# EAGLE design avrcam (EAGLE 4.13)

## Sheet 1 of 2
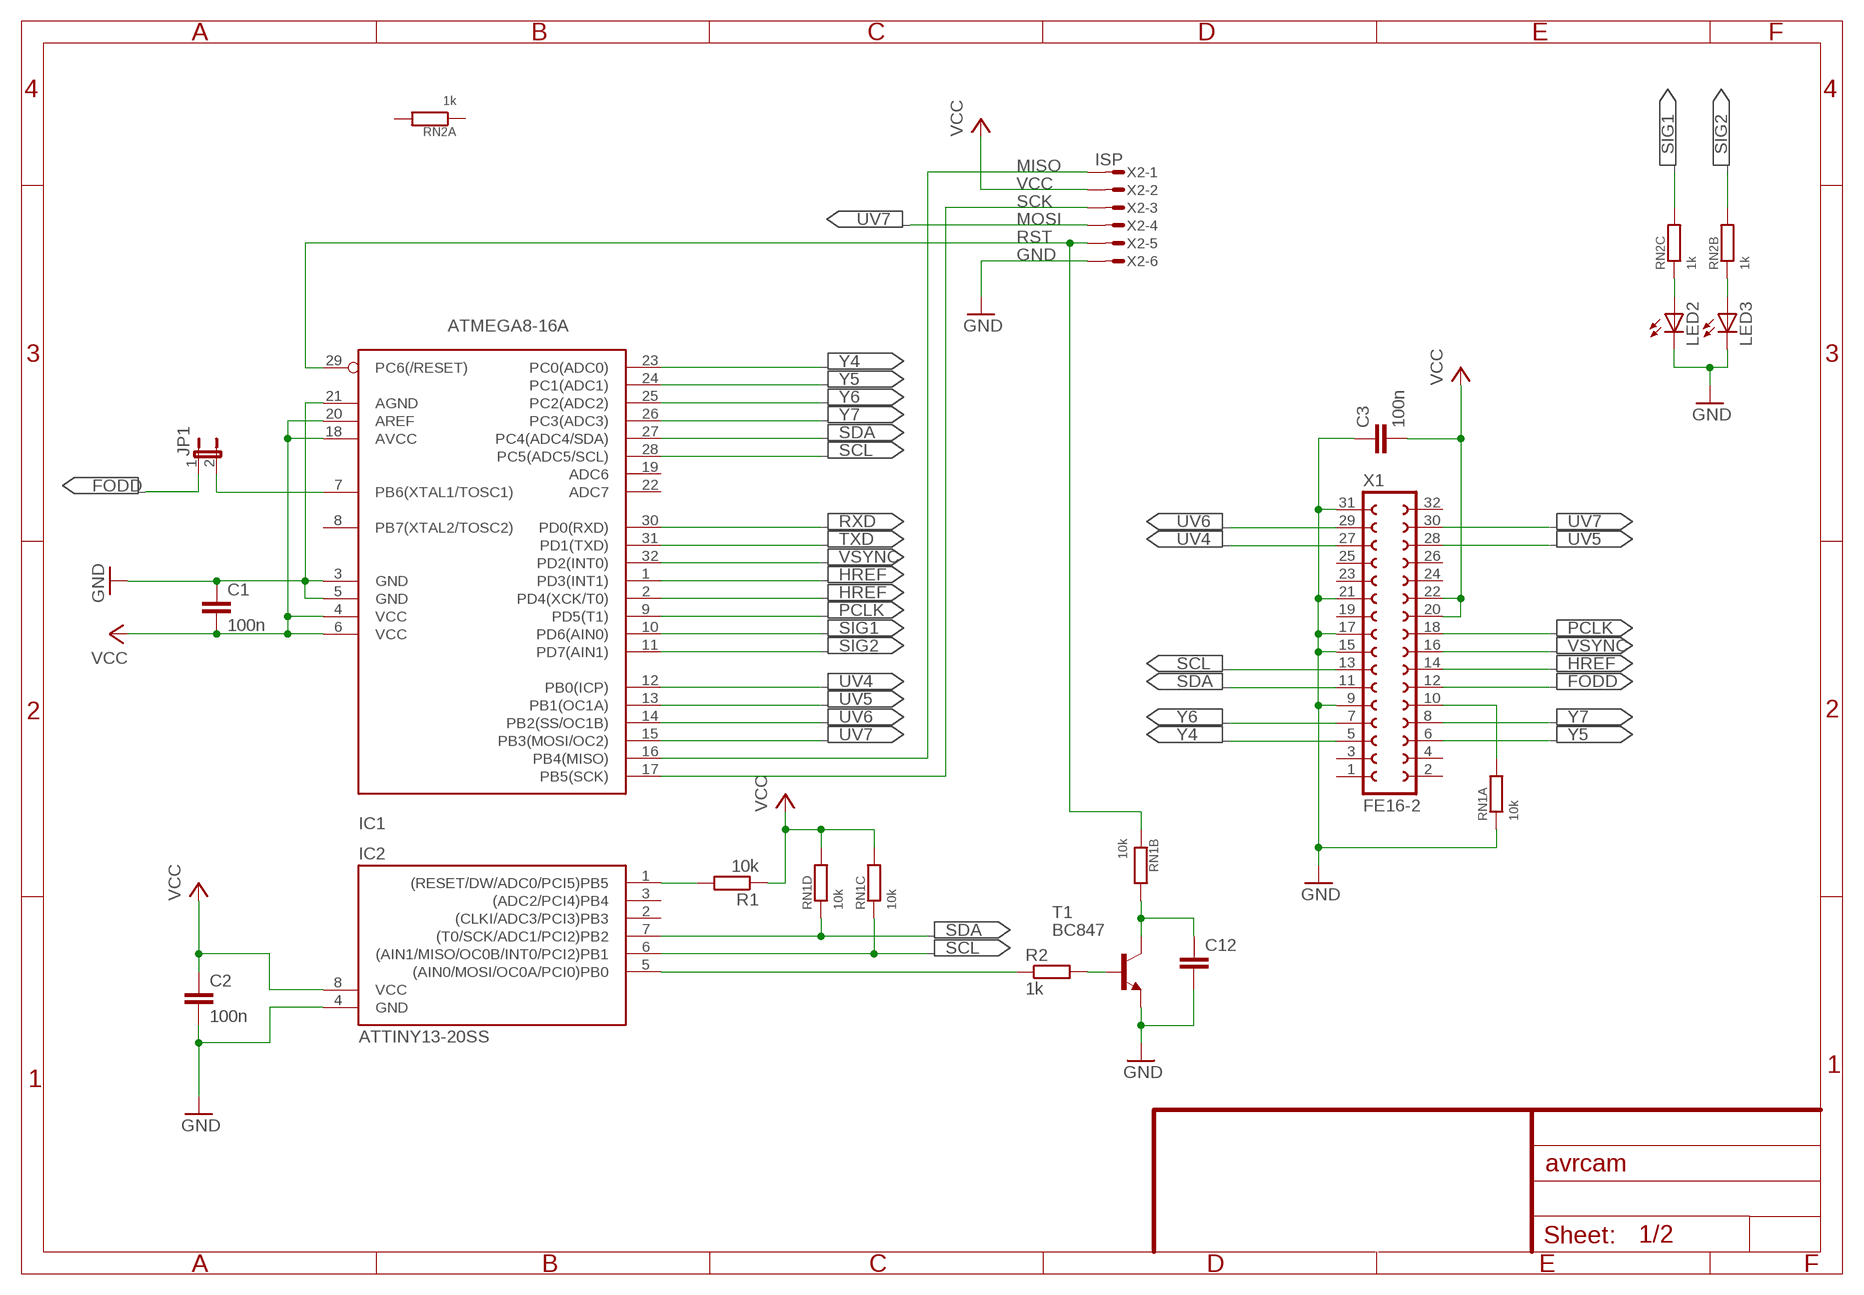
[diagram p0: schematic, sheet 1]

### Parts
C1  100n  C-EUC0603K  [C0603K]
C2  100n  C-EUC0603K  [C0603K]
C3  100n  C-EUC0603K  [C0603K]
C12  C-EUC0603K  [C0603K]
IC1  ATMEGA8-16A  [TQFP32-08]
IC2  ATTINY13-20SS  [SO08]
JP1  JP1E  [JP1]
LED2  LEDCHIPLED_1206  [CHIPLED_1206]
LED3  LEDCHIPLED_1206  [CHIPLED_1206]
R1  10k  R-EU_R0805  [R0805]
R2  1k  R-EU_R0805  [R0805]
RN1  10k  SMDNET4SINGLE  [SMDNET4]
RN2  1k  SMDNET4SINGLE  [SMDNET4]
T1  BC847  [SOT23]
X1  FE16-2  [FE16-2]
X2  ISP  MICROMATCH-6  [MICROMATCH-6]

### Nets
FODD: JP1.1 X1.12
GND: C1.1 C2.2 C3.1 C12.2 IC1.3(GND) IC1.5(GND) IC1.21(AGND) IC2.4(GND) LED2.C LED3.C RN1.1 T1.2(E) X1.9 X1.15 X1.17 X1.21 X1.31 X2.6 ; also sheet 2
HREF: IC1.1(PD3(INT1)) IC1.2(PD4(XCK/T0)) X1.14
MISO: IC1.16(PB4(MISO)) X2.1
N$1: IC2.1((RESET/DW/ADC0/PCI5)PB5) R1.2
N$2: IC1.7(PB6(XTAL1/TOSC1)) JP1.2
N$6: IC2.5((AIN0/MOSI/OC0A/PCI0)PB0) R2.1
N$9: R2.2 T1.1(B)
N$14: C12.1 RN1.7 T1.3(C)
N$15: LED3.A RN2.2
N$16: LED2.A RN2.3
N$18: RN1.8 X1.10
PCLK: IC1.9(PD5(T1)) X1.18
RST: IC1.29(PC6(/RESET)) RN1.2 X2.5
RXD: IC1.30(PD0(RXD)) ; also sheet 2
SCK: IC1.17(PB5(SCK)) X2.3
SCL: IC1.28(PC5(ADC5/SCL)) IC2.6((AIN1/MISO/OC0B/INT0/PCI2)PB1) RN1.3 X1.13
SDA: IC1.27(PC4(ADC4/SDA)) IC2.7((T0/SCK/ADC1/PCI2)PB2) RN1.4 X1.11
SIG1: IC1.10(PD6(AIN0)) RN2.6
SIG2: IC1.11(PD7(AIN1)) RN2.7
TXD: IC1.31(PD1(TXD)) ; also sheet 2
UV4: IC1.12(PB0(ICP)) X1.27
UV5: IC1.13(PB1(OC1A)) X1.28
UV6: IC1.14(PB2(SS/OC1B)) X1.29
UV7: IC1.15(PB3(MOSI/OC2)) X1.30 X2.4
VCC: C1.2 C2.1 C3.2 IC1.4(VCC) IC1.6(VCC) IC1.18(AVCC) IC1.20(AREF) IC2.8(VCC) R1.1 RN1.5 RN1.6 X1.20 X1.22 X2.2 ; also sheet 2
VSYNC: IC1.32(PD2(INT0)) X1.16
Y4: IC1.23(PC0(ADC0)) X1.5
Y5: IC1.24(PC1(ADC1)) X1.6
Y6: IC1.25(PC2(ADC2)) X1.7
Y7: IC1.26(PC3(ADC3)) X1.8
Unconnected: IC1.8(PB7(XTAL2/TOSC2)) IC1.19(ADC6) IC1.22(ADC7) IC2.2((CLKI/ADC3/PCI3)PB3) IC2.3((ADC2/PCI4)PB4) X1.1 X1.2 X1.3 X1.4 X1.19 X1.23 X1.24 X1.25 X1.26 X1.32

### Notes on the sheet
- MOSI

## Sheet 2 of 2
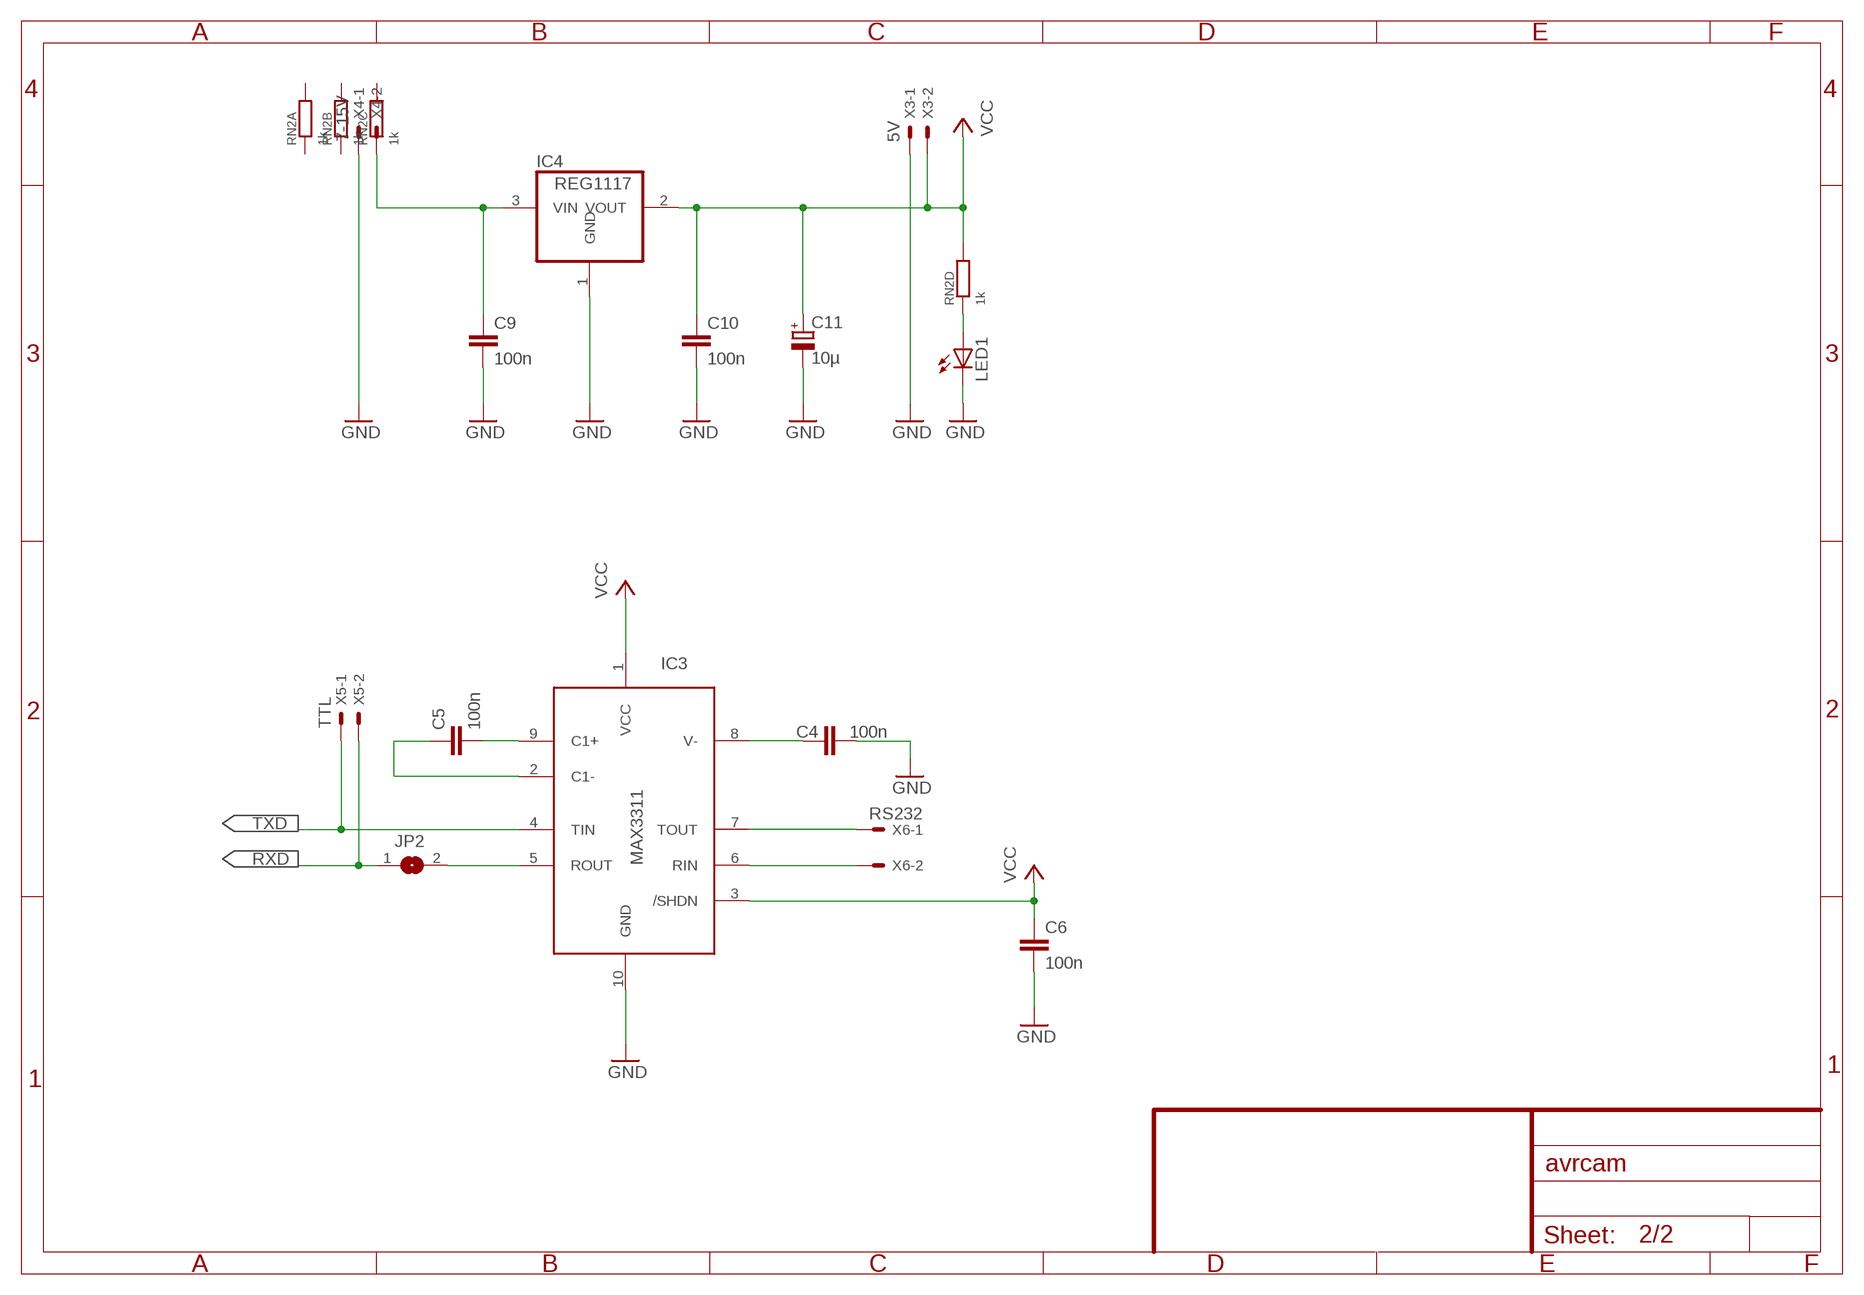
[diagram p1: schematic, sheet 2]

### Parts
C4  100n  C-EUC0603K  [C0603K]
C5  100n  C-EUC0603K  [C0603K]
C6  100n  C-EUC0603K  [C0603K]
C9  100n  C-EUC0603K  [C0603K]
C10  100n  C-EUC0603K  [C0603K]
C11  10µ  CPOL-EUCT3216  [CT3216]
IC3  MAX3311  [UMAX10]
IC4  REG1117  [SOT223]
JP2  SJ  [SJ]
LED1  LEDCHIPLED_1206  [CHIPLED_1206]
X3  5V  22-23-2021  [22-23-2021]
X4  7-15V  22-23-2021  [22-23-2021]
X5  TTL  22-23-2021  [22-23-2021]
X6  RS232  22-23-2021  [22-23-2021]

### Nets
GND: C4.2 C6.2 C9.2 C10.2 C11.- IC3.10(GND) IC4.1(GND) LED1.C X3.1 X4.1 ; also sheet 1
N$3: C5.2 IC3.9(C1+)
N$4: C5.1 IC3.2(C1-)
N$5: C4.1 IC3.8(V-)
N$7: IC3.5(ROUT) JP2.2
N$8: C9.1 IC4.3(VIN) X4.2
N$10: IC3.6(RIN) X6.2
N$11: IC3.7(TOUT) X6.1
N$12: LED1.A RN2.4
RXD: JP2.1 X5.2 ; also sheet 1
TXD: IC3.4(TIN) X5.1 ; also sheet 1
VCC: C6.1 C10.1 C11.+ IC3.1(VCC) IC3.3(/SHDN) IC4.2(VOUT) RN2.5 X3.2 ; also sheet 1
Unconnected: RN2.1 RN2.8

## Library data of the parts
C1-C6 C9 C10 C12 = rcl:C-EU: CAPACITOR, European symbol
C11 = rcl:CPOL-EU: POLARIZED CAPACITOR, European symbol
IC1 = avr:ATMEGA8: MICROCONTROLLER 8 Kbytes FLASH 1 kbytes SRAM 512 bytes EEPROM USART 6-channel 10 bit ADC 2-channel 8 bit ADC
IC2 = avr:ATTINY13: MICROCONTROLLER 1 Kbytes FLASH 64 bytes EEPROM 64 bytes RAM 4-channel 10 bit ADC
IC3 = maxim_updated:MAX3311
IC4 = burr-brown:REG1117: 800mA and 1A Low Dropout (LDO) Positive Regulator 1.8V, 2.5V, 2.85V, 3.3V, 5V, and Adj
JP1 = jumper:JP1E: JUMPER
JP2 = jumper:SJ: SMD solder JUMPER
LED1-LED3 = led:LED: LED
R1 R2 = rcl:R-EU_: RESISTOR, European symbol
RN1 RN2 = ResNetSMD:SMDNET4SINGLE
T1 = transistor:BC847: NPN TRANSISTOR
X1 = con-lsta:FE16-2
X2 = con-amp-micromatch:MICROMATCH-6: MicroMaTch 6 7-215464-6 / 0-215464-6 Drawing Number C-215464 DDEController.pdf
X3-X6 = con-molex:22-23-2021: .100" (2.54mm) Center Header - 2 Pin

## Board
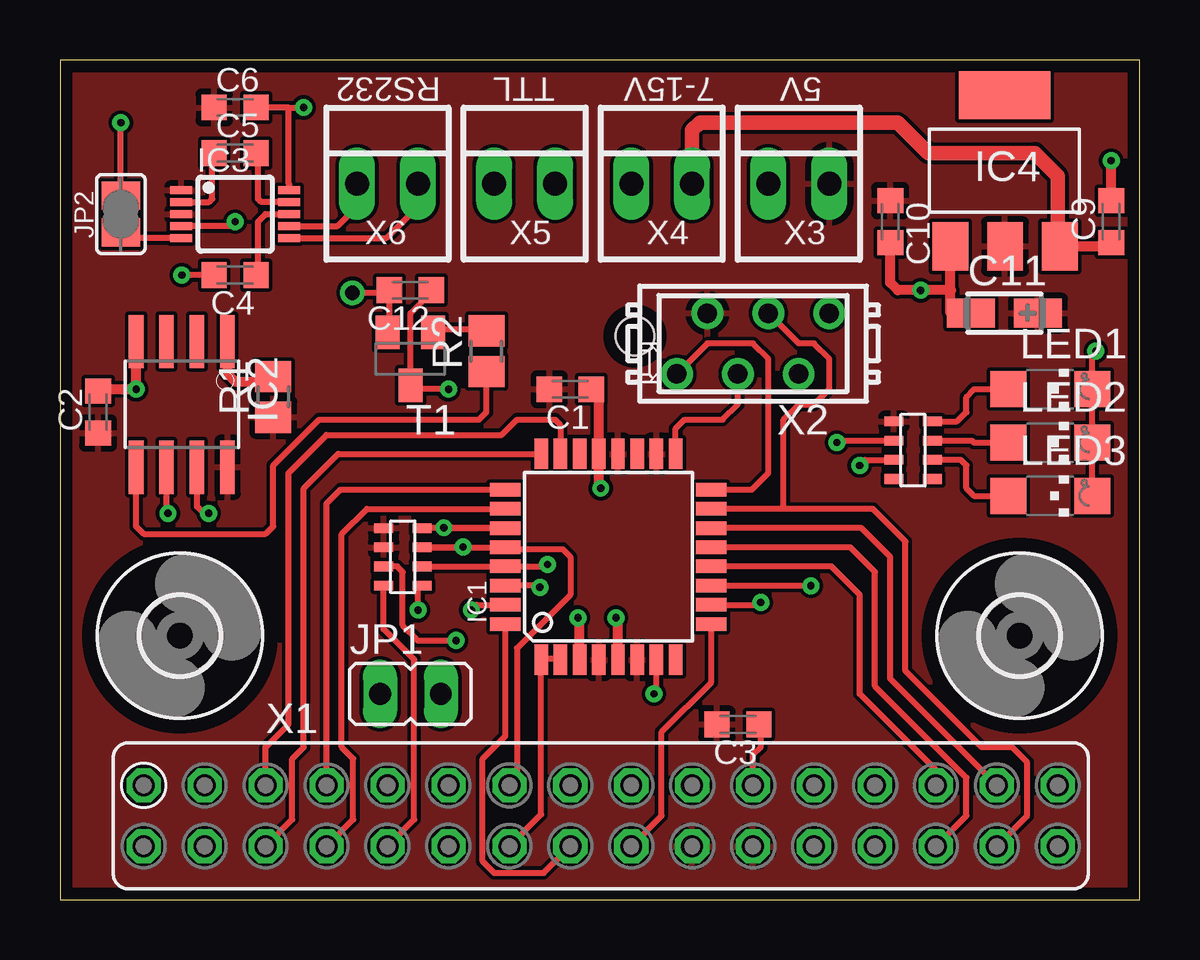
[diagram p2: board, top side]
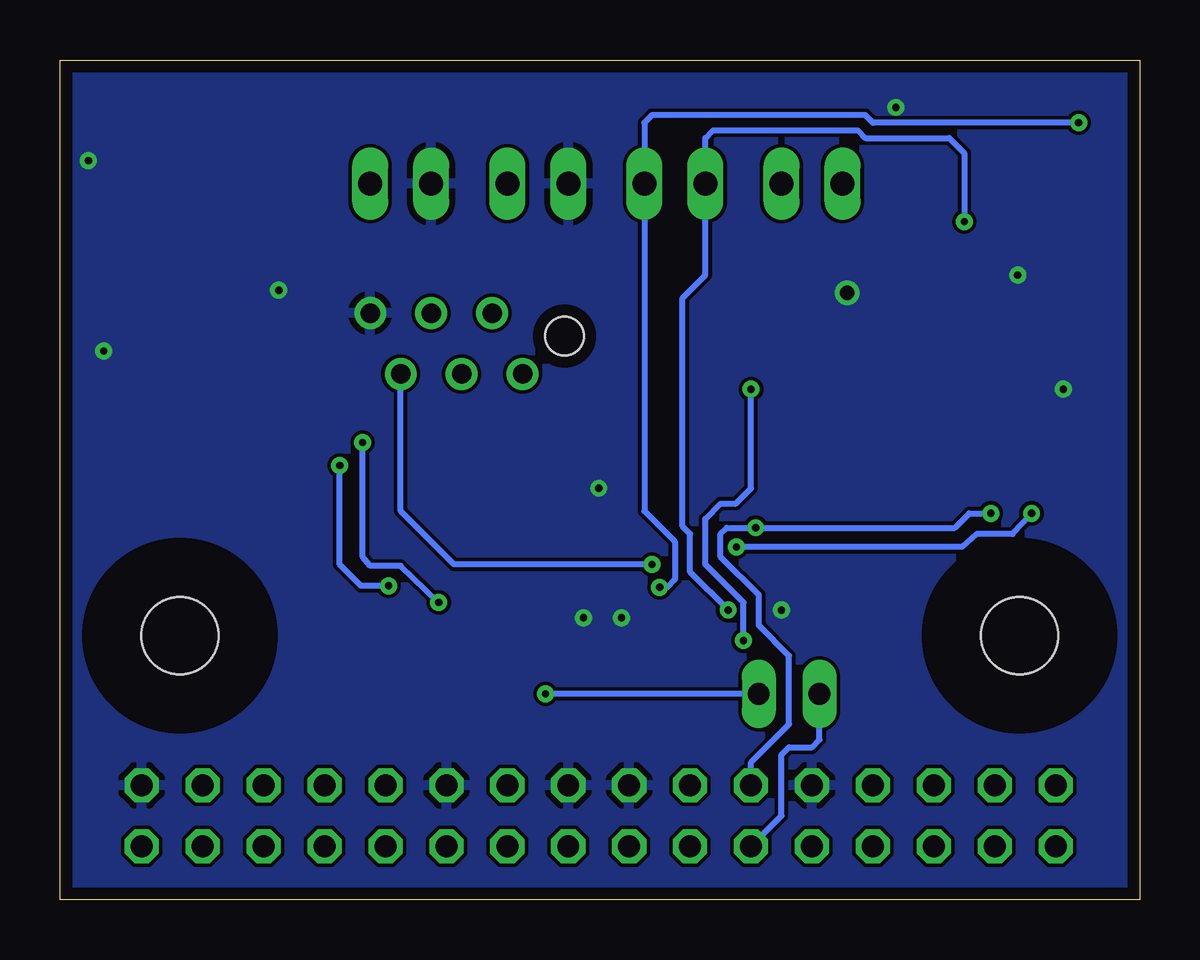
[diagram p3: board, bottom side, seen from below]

Size 45 x 35 mm. Coordinates in mm from the lower left corner, seen from the top.
Outline: 0,0 45,0 45,35 0,35 0,0
Copper layers (1*16): Top 0.035mm / dielectric 1.5mm / Bottom 0.035mm
Design rules "default": minimum track width 10mil, minimum drill 24mil, track to track 6mil, track to pad 6mil, pad to pad 6mil, via to via 6mil, smd to smd 6mil, copper to edge 20mil, drill to drill 5mil, minimum pad ring 10mil, minimum via ring 8mil, stop-mask expansion 4mil, vias tented up to drill 0mil, thermal gap 10mil
Holes 1.6 mm at 23.97,23.5

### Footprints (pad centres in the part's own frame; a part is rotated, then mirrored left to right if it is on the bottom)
C0603K = smd 1.05 x 1.08: 1 -0.875,0; 2 0.875,0
CT3216 = smd 2 x 1.2: + 1.4,0; - -1.4,0
TQFP32-08 = smd 1.27 x 0.559: 1 -4.293,2.8; 2 -4.293,2; 3 -4.293,1.2; 4 -4.293,0.4; 5 -4.293,-0.4; 6 -4.293,-1.2; 7 -4.293,-2; 8 -4.293,-2.8; 17 4.293,-2.8; 18 4.293,-2; 19 4.293,-1.2; 20 4.293,-0.4; 21 4.293,0.4; 22 4.293,1.2; 23 4.293,2; 24 4.293,2.8 | smd 0.559 x 1.27: 9 -2.8,-4.293; 10 -2,-4.293; 11 -1.2,-4.293; 12 -0.4,-4.293; 13 0.4,-4.293; 14 1.2,-4.293; 15 2,-4.293; 16 2.8,-4.293; 25 2.8,4.293; 26 2,4.293; 27 1.2,4.293; 28 0.4,4.293; 29 -0.4,4.293; 30 -1.2,4.293; 31 -2,4.293; 32 -2.8,4.293
SO08 = smd 0.61 x 2.21: 1 -1.905,-2.616; 2 -0.635,-2.616; 3 0.635,-2.616; 4 1.905,-2.616; 5 1.905,2.616; 6 0.635,2.616; 7 -0.635,2.616; 8 -1.905,2.616
UMAX10 = smd 0.32 x 0.9: 1 -1,-2.25; 2 -0.5,-2.25; 3 0,-2.25; 4 0.5,-2.25; 5 1,-2.25; 6 1,2.25; 7 0.5,2.25; 8 0,2.25; 9 -0.5,2.25; 10 -1,2.25
SOT223 = smd 1.499 x 2.007: 1 -2.261,-3.15; 2 0.025,-3.15; 3 2.311,-3.15 | smd 3.81 x 2.007: 4 0,3.15
JP1 = drill 0.914 long: 1 0,-1.27; 2 0,1.27
SJ = smd 1.168 x 1.6: 1 -0.762,0; 2 0.762,0
CHIPLED_1206 = smd 1.5 x 1.5: A 0,-1.75; C 0,1.75
R0805 = smd 1.3 x 1.5: 1 -0.85,0; 2 0.85,0
SMDNET4 = smd 0.8 x 0.4: 1 -0.8,1.2; 2 -0.8,0.4; 3 -0.8,-0.4; 4 -0.8,-1.2; 5 0.8,-1.2; 6 0.8,-0.4; 7 0.8,0.4; 8 0.8,1.2
SOT23 = smd 1 x 1.4: 1 -0.95,-1.1; 2 0.95,-1.1; 3 0,1.1
3,2 = hole 3.2: 0,0
FE16-2 = drill 0.914 octagon: 1 -19.05,1.27; 2 -19.05,-1.27; 3 -16.51,1.27; 4 -16.51,-1.27; 5 -13.97,1.27; 6 -13.97,-1.27; 7 -11.43,1.27; 8 -11.43,-1.27; 9 -8.89,1.27; 10 -8.89,-1.27; 11 -6.35,1.27; 12 -6.35,-1.27; 13 -3.81,1.27; 14 -3.81,-1.27; 15 -1.27,1.27; 16 -1.27,-1.27; 17 1.27,1.27; 18 1.27,-1.27; 19 3.81,1.27; 20 3.81,-1.27; 21 6.35,1.27; 22 6.35,-1.27; 23 8.89,1.27; 24 8.89,-1.27; 25 11.43,1.27; 26 11.43,-1.27; 27 13.97,1.27; 28 13.97,-1.27; 29 16.51,1.27; 30 16.51,-1.27; 31 19.05,1.27; 32 19.05,-1.27
MICROMATCH-6 = drill 0.813 round: 1 3.175,1.27; 2 1.905,-1.27; 3 0.635,1.27; 4 -0.635,-1.27; 5 -1.905,1.27; 6 -3.175,-1.27
22-23-2021 = drill 1 long: 1 -1.27,0; 2 1.27,0

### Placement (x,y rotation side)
C1  21.27,21.27 180 top
C2  1.59,20.32 90 top
C3  28.26,7.3 180 top
C4  7.3,26.04 180 top
C5  7.3,31.11 0 top
C6  7.3,33.02 0 top
C9  43.81,28.26 90 top
C10  34.61,28.26 270 top
C11  39.37,24.45 0 top
C12  14.61,25.4 180 top
IC1  22.86,14.29 90 top
IC2  5.08,20.64 180 top
IC3  7.3,28.57 270 top
IC4  39.37,30.38 0 top
JP1  14.61,8.57 270 top
JP2  2.54,28.57 270 top
LED1  41.27,21.27 270 top
LED2  41.27,19.05 270 top
LED3  41.27,16.83 270 top
R1  8.89,20.95 90 top
R2  17.78,22.86 90 top
RN1  14.29,14.29 180 top
RN2  35.56,18.73 180 top
T1  14.61,22.54 180 top
U$1  [3,2]  5,11 0 top
U$2  [3,2]  40,11 0 top
X1  22.54,3.49 0 top
X2  28.89,23.18 180 top
X3  30.8,29.84 0 top
X4  25.08,29.84 0 top
X5  19.37,29.84 0 top
X6  13.65,29.84 0 top

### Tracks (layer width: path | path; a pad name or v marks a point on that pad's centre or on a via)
FODD
  Bottom 0.254: JP1.1 13.34,6.67 13.65,6.35 14.61,6.35 14.92,6.03 14.92,3.49 X1.12
GND  (via drill 0.3, 0.61)
  Top 0.254: 9.53,33.02 C6.2 | IC3.10 9.55,29.82 9.53,29.84 9.53,33.02 | 9.53,33.02 v10.16,33.02 | C4.2 v5.08,26.04 | LED3.C 43.02,18.89 43.18,19.05 LED2.C 43.02,21.12 43.18,21.27 LED1.C 43.02,22.7 v43.18,22.86 | T1.2 13.72,24.08 13.72,24.99 C12.2 13.41,25.3 v12.19,25.3 | 15.24,13.11 RN1.1 14.85,13.09 14.92,13.02 v14.92,12.06 | X1.21 28.89,6.03 29.21,6.35 29.21,6.99 29.13,7.06 C3.1
  Top 0.406: IC1.3 21.66,11.68 arc90 v21.59,11.75 | IC1.5 23.26,11.66 arc90 v23.18,11.75 | v22.54,17.14 arc-90 22.46,17.23 IC1.21 22.46,20.87 22.23,21.27 C1.1 | IC2.4 v3.17,21.27 1.59,21.27 C2.2 | C10.2 34.61,25.72 34.92,25.4 v35.88,25.4 37.11,25.4 | 37.11,25.4 37.11,24.49 37.15,24.45 C11.- | 37.11,25.4 IC4.1 | 37.11,25.4 37.15,25.4 | C9.2 v43.81,30.8
  pour Bottom: 0,35.01 45.09,35.01 45.09,0 0,0
HREF
  Top 0.254: IC1.2 20.73,10.06 20.12,10.06 IC1.1 20.06,3.55 X1.14
MISO
  Top 0.254: X2.1 26.99,23.18 28.89,23.18 29.53,22.54 29.53,17.78 28.84,17.09 IC1.16
N$1
  Top 0.406: IC2.1 6.99,21.91 7.3,21.59 8.57,21.59 8.79,21.8 R1.2
N$2  (via drill 0.3)
  Top 0.254: IC1.7 24.86,8.67 v24.77,8.57
  Bottom 0.254: JP1.2 v24.77,8.57
N$3
  Top 0.254: IC3.9 8.39,29.07 8.26,29.21 8.26,31.11 C5.2
N$4
  Top 0.254: IC3.2 6.21,29.07 6.35,29.21 6.35,31.11 C5.1
N$5
  Top 0.254: IC3.8 8.57,28.57 8.26,28.26 8.26,26.04 C4.1
N$6
  Top 0.254: R2.1 17.78,20.32 17.46,20 10.79,20 8.89,18.1 8.89,15.56 8.57,15.24 3.49,15.24 3.17,15.56 IC2.5
N$7
  Top 0.254: JP2.2 2.54,27.62 2.59,27.57 IC3.5
N$8
  Top 0.406: C9.1 43.81,27.3 43.79,27.33 43.8,27.3 43.8,27.23 IC4.3
  Top 0.61: X4.2 26.35,32.07 26.67,32.38 34.92,32.38 36.2,31.11 40.64,31.11 41.59,30.16 41.59,27.62 41.68,27.53 IC4.3
N$9
  Top 0.254: T1.1 15.85,23.77 17.07,23.77 R2.2
N$10
  Top 0.254: IC3.6 13.61,27.57 14.92,28.89 X6.2
N$11
  Top 0.254: IC3.7 11.56,28.07 12.38,28.89 X6.1
N$12
  Top 0.254: RN2.4 37.4,19.93 37.78,20.32 37.78,20.95 38.1,21.27 LED1.A
N$14  (via drill 0.3)
  Top 0.254: C12.1 15.56,25.4 14.61,24.45 T1.3 14.61,21.27 v16.19,21.27 | RN1.7 14.05,13.89 14.29,13.65 14.29,11.43 14.92,10.79 v16.51,10.79
  Bottom 0.254: v16.51,10.79 16.51,12.38 18.1,13.97 18.1,15.88 17.46,16.51 16.83,16.51 16.19,17.14 v16.19,21.27
N$15
  Top 0.254: RN2.2 37.55,18.33 37.78,18.1 37.78,17.14 38.1,16.83 LED3.A
N$16
  Top 0.254: RN2.3 38.02,19.13 38.1,19.05 LED2.A
N$18
  Top 0.254: RN1.8 13.49,11.28 14.76,10 14.76,3.33 X1.10
PCLK
  Top 0.254: IC1.9 27.15,9.05 25.08,6.99 25.08,3.49 X1.18
RST  (via drill 0.3)
  Top 0.254: RN1.2 18.33,13.89 18.41,13.97 18.5,13.89 IC1.29 20.24,13.89 v20.32,13.97
  Bottom 0.254: v20.32,13.97 28.57,13.97 30.8,16.19 X2.5
RXD  (via drill 0.3)
  Top 0.254: JP2.1 v2.54,32.38 | IC1.30 19.93,13.09 v20,13.02
  Bottom 0.254: v2.54,32.38 11.11,32.38 11.43,32.7 20.32,32.7 20.64,32.38 X5.2 20.64,16.19 19.37,14.92 19.37,13.34 19.68,13.02 v20,13.02
SCK
  Top 0.254: IC1.17 25.66,19.63 26.04,20 27.62,20 28.26,20.64 X2.3
SCL  (via drill 0.3)
  Top 0.254: 18.41,14.61 18.5,14.69 IC1.28 | 18.41,14.61 18.33,14.69 RN1.3 16.79,14.69 v16.8,14.7 | IC2.6 4.45,16.25 v4.5,16.1 | 18.41,14.61 20.95,14.61 21.27,14.29 21.27,12.7 19.05,10.48 19.05,5.08 X1.13
  Bottom 0.254: v16.8,14.7 7.4,14.7 6.8,15.24 5.3,15.24 v4.5,16.1
SDA  (via drill 0.3)
  Top 0.254: 18.48,15.49 18.41,15.56 18.34,15.49 | 18.48,15.49 IC1.27 18.57,15.4 | IC2.7 5.71,16.39 6,16.1 v6.2,16.1 | 18.57,15.4 | 18.34,15.49 RN1.4 | 18.34,15.49 18.48,15.49 | 18.48,15.49 18.57,15.4 | 18.34,15.49 16,15.49 v16,15.5
  Bottom 0.254: v6.2,16.1 7.1,16.1 7.7,15.5 15.9,15.5 v16,15.5 17.2,15.5 17.46,15.24 17.46,14.29 15.88,12.7 15.88,11.43 14.61,10.16 14.61,7.3 16.19,5.71 X1.11
SIG1  (via drill 0.3)
  Top 0.254: RN2.6 32.47,19.13 v32.38,19.05 | IC1.10 29.11,12.29 v29.21,12.38
  Bottom 0.254: v32.38,19.05 32.38,14.29 32.07,13.91 30.8,13.91 v29.21,12.38
SIG2  (via drill 0.3)
  Top 0.254: RN2.7 33.57,18.33 v33.34,18.1 | IC1.11 31.3,13.09 v31.3,13.08
  Bottom 0.254: v33.34,18.1 33.34,13.97 32.45,13.08 v31.3,13.08
TXD  (via drill 0.3)
  Top 0.254: IC3.4 7.12,28.07 v7.3,28.26 | IC1.31 17.37,12.29 v17.14,12.06
  Bottom 0.254: v7.3,28.26 7.3,31.11 7.94,31.75 11.43,31.75 11.75,32.07 17.78,32.07 18.1,31.75 X5.1 18.1,26.04 19.05,25.08 19.05,15.56 18.73,15.24 18.73,13.65 v17.14,12.06
UV4
  Top 0.254: X1.27 36.51,5.4 33.34,8.57 33.34,12.7 32.15,13.89 IC1.12
UV5
  Top 0.254: X1.28 37.78,3.49 37.78,5.08 33.97,8.89 33.97,13.65 32.94,14.69 IC1.13
UV6
  Top 0.254: X1.29 34.61,9.21 34.61,14.29 33.41,15.49 IC1.14
UV7
  Top 0.254: X1.30 40.32,3.49 40.32,5.71 39.69,6.35 38.42,6.35 35.24,9.53 35.24,14.92 33.88,16.29 30.16,16.29 | 30.16,16.29 IC1.15 | X2.4 30.8,23.18 31.43,23.18 32.07,22.54 32.07,21.27 31.43,20.64 30.8,20.64 30.16,20 30.16,16.29
VCC
  pour Top: 0,35.01 45.09,35.01 45.09,0 0,0
VSYNC
  Top 0.254: IC1.32 18.57,6.82 17.62,5.87 17.62,1.59 18.1,1.11 20.16,1.11 X1.16
Y4
  Top 0.254: IC1.23 20.86,19.78 20.64,20 19.05,20 18.41,19.37 11.11,19.37 9.53,17.78 9.53,7.3 8.57,6.35 X1.5
Y5
  Top 0.254: IC1.24 11.6,18.58 10.16,17.14 10.16,6.35 9.68,5.87 9.68,3.33 X1.6
Y6
  Top 0.254: IC1.25 11.69,17.09 11.11,16.51 X1.7
Y7
  Top 0.254: IC1.26 12.79,16.29 11.75,15.24 11.75,6.35 12.22,5.87 12.22,3.33 X1.8

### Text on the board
tPlace: RS232 | TTL | 7-15V | 5V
